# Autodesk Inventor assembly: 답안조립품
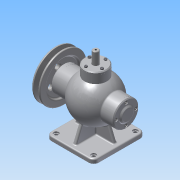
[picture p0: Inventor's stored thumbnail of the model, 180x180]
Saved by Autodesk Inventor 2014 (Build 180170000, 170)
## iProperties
Created: 2017-01
Part Number: 답안조립품
Document SubType Name: Assembly
Designer: ksu
Author: ksu
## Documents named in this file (19)
- C:\Users\ksu\Desktop\470118V1006\답안조립품.iam
- C:\Users\ksu\Desktop\470118V1006\01 본체.ipt
- C:\Users\ksu\Desktop\470118V1006\V-벨트풀리.ipt
- C:\Users\ksu\Desktop\470118V1006\뒤커버.ipt
- C:\Users\ksu\Desktop\470118V1006\편심축.ipt
- C:\Users\ksu\Desktop\470118V1006\키 4 x 4 x 12.ipt
- C:\Users\ksu\Desktop\470118V1006\베어링- 6202.ipt
- KS B 2023 - 6202 - 15 x 35 x 11 - 7.8.ipt
- C:\Users\ksu\Desktop\470118V1006\오일실 15 30 7.ipt
- C:\Users\ksu\Desktop\470118V1006\앞커버.ipt
- C:\Users\ksu\Desktop\470118V1006\멈춤링- 35x1.6.ipt
- KS B 1336 - 35x1.6.ipt
- C:\Users\ksu\Desktop\470118V1006\멈춤링- 15 x 1.ipt
- C:\Users\ksu\Desktop\470118V1006\볼트 M4 x 16.ipt
- C:\Users\ksu\Desktop\470118V1006\슬라이드.ipt
- C:\Users\ksu\Desktop\470118V1006\상부커버.ipt
- C:\Users\ksu\Desktop\470118V1006\볼트 M4 x 12.ipt
- C:\Users\ksu\Desktop\470118V1006\너트 M8.ipt
- C:\Users\ksu\Desktop\470118V1006\부시.ipt
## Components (17 placed, 6 different names)
1. 01 본체:1 — Mate:15, Mate:23, Mate:24, Mate:25, Mate:26, Mate:27, Mate:28
2. V-벨트풀리:1 — Mate:21, Mate:22, Flush:3, Insert:11
3. KS B 2023 - 6202 - 15 x 35 x 11 - 7.8:1 — Mate:4, Flush:1, Mate:6
4. KS B 2023 - 6202 - 15 x 35 x 11 - 7.8:2 — Mate:18, Mate:19, Mate:20
5. KS B 1336 - 35x1.6:1 — Mate:5, Mate:6
6. ISO 4762 M4 x 16:1 — Mate:8, Mate:11
7. ISO 4762 M4 x 16:2 — Mate:9, Mate:14
8. ISO 4762 M4 x 16:3 — Mate:10, Mate:13
9. ISO 4762 M4 x 16:4 — Mate:7, Mate:12
10. KS B 1021 - 에 따름 ISO 1207 - 미터 A  M 4 x 12:1 — Insert:5
11. KS B 1021 - 에 따름 ISO 1207 - 미터 A  M 4 x 12:2 — Insert:3
12. KS B 1021 - 에 따름 ISO 1207 - 미터 A  M 4 x 12:3 — Insert:2
13. KS B 1021 - 에 따름 ISO 1207 - 미터 A  M 4 x 12:4 — Insert:4
14. ISO 4762 M4 x 16:5 — Insert:7
15. ISO 4762 M4 x 16:6 — Insert:8
16. ISO 4762 M4 x 16:7 — Insert:9
17. ISO 4762 M4 x 16:8 — Insert:6
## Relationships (34: Mate 23, Insert 9, Flush 2)
- Mate:4: KS B 2023 - 6202 - 15 x 35 x 11 - 7.8:1
- Flush:1: KS B 2023 - 6202 - 15 x 35 x 11 - 7.8:1
- Mate:5: KS B 1336 - 35x1.6:1
- Mate:6: KS B 2023 - 6202 - 15 x 35 x 11 - 7.8:1 ↔ KS B 1336 - 35x1.6:1
- Mate:7: ISO 4762 M4 x 16:4
- Mate:8: ISO 4762 M4 x 16:1
- Mate:9: ISO 4762 M4 x 16:2
- Mate:10: ISO 4762 M4 x 16:3
- Mate:11: ISO 4762 M4 x 16:1
- Mate:12: ISO 4762 M4 x 16:4
- Mate:13: ISO 4762 M4 x 16:3
- Mate:14: ISO 4762 M4 x 16:2
- Insert:2: KS B 1021 - 에 따름 ISO 1207 - 미터 A  M 4 x 12:3
- Insert:3: KS B 1021 - 에 따름 ISO 1207 - 미터 A  M 4 x 12:2
- Insert:4: KS B 1021 - 에 따름 ISO 1207 - 미터 A  M 4 x 12:4
- Insert:5: KS B 1021 - 에 따름 ISO 1207 - 미터 A  M 4 x 12:1
- Mate:15: 01 본체:1
- Insert:6: ISO 4762 M4 x 16:8
- Insert:7: ISO 4762 M4 x 16:5
- Insert:8: ISO 4762 M4 x 16:6
- Insert:9: ISO 4762 M4 x 16:7
- Mate:18: KS B 2023 - 6202 - 15 x 35 x 11 - 7.8:2
- Mate:19: KS B 2023 - 6202 - 15 x 35 x 11 - 7.8:2
- Mate:20: KS B 2023 - 6202 - 15 x 35 x 11 - 7.8:2
- Mate:21: V-벨트풀리:1
- Mate:22: V-벨트풀리:1
- Flush:3: V-벨트풀리:1
- Mate:23: 01 본체:1
- Mate:24: 01 본체:1
- Mate:25: 01 본체:1
- Mate:26: 01 본체:1
- Insert:11: V-벨트풀리:1
- Mate:27: 01 본체:1
- Mate:28: 01 본체:1
